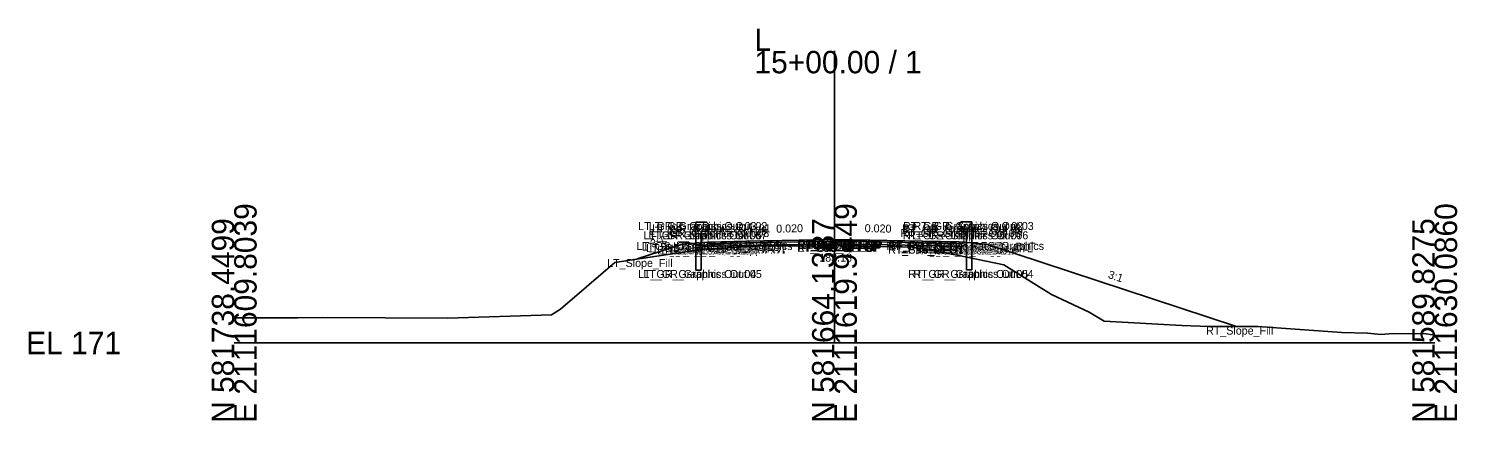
# Model space of a CAD drawing. Extents: x -26 to 3453, y -333 to 9539.
# Drawn here: x -25.7 to 152.8, y 5490.3 to 5539.3 of the extents above; entities that cross this region are included whole.
import ezdxf

# ---------------------------------------------------------------- set-up
doc = ezdxf.new("R2010")
doc.units = 0
for name, color, linetype in [('Default', 7, 'Continuous'), ('Exist Cross Section Cell', 7, 'Continuous'), ('Exist XS Center Line Elevation Label', 7, 'Continuous'), ('Exist XS Ground Line', 7, 'Continuous'), ('Prop CMT Guardrail Graphics', 7, 'Continuous'), ('Prop CMT Pvmt Course 1', 7, 'Continuous'), ('Prop CMT Pvmt Course 2', 7, 'Continuous'), ('Prop CMT Pvmt Course 3', 7, 'Continuous'), ('Prop CMT Pvmt Surface', 7, 'Continuous'), ('Prop CMT Pvmt Surface Shoulder', 7, 'Continuous'), ('Prop CMT Shld Paved Course 1', 7, 'Continuous'), ('Prop CMT Shld Paved Course 2', 7, 'Continuous'), ('Prop CMT Shld Paved Course 3', 7, 'Continuous'), ('Prop CMT Slope Grass', 7, 'Continuous'), ('Prop CMT Subgrade Earthwork', 7, 'Continuous'), ('Prop XS SE Text', 7, 'Continuous'), ('Prop XS Side Slope Text', 7, 'Continuous'), ('Scratch_Level_0', 7, 'Continuous')]:
    doc.layers.add(name, color=color, linetype=linetype)

msp = doc.modelspace()

# ---------------------------------------------------------------- linework, layer by layer
at = {"layer": 'Exist Cross Section Cell'}
for p, q in [((75, 5500), (75, 5536.54)), ((0, 5500), (75, 5500)), ((75, 5500), (150, 5500))]:
    msp.add_line(p, q, dxfattribs=at)
at = {"layer": 'Exist XS Ground Line'}
for p, q in [((47.57, 5510.09), (57.21, 5511.54)), ((57.21, 5511.54), (58.81, 5511.73)), ((58.81, 5511.73), (65.21, 5512.13)), ((65.21, 5512.13), (73.41, 5512.17)), ((73.41, 5512.17), (74.81, 5512.18)), ((74.81, 5512.18), (76.25, 5512.15)), ((76.25, 5512.15), (84.84, 5511.99)), ((84.84, 5511.99), (88.49, 5511.31)), ((88.49, 5511.31), (90.54, 5510.96)), ((40.79, 5504.24), (47.57, 5510.09)), ((90.54, 5510.96), (96.15, 5509.77)), ((96.15, 5509.77), (102.1, 5506.08)), ((102.1, 5506.08), (106.81, 5503.84)), ((39.65, 5503.54), (40.79, 5504.24)), ((0, 5503.15), (7.95, 5503.16)), ((7.95, 5503.16), (11.02, 5503.21)), ((11.02, 5503.21), (26.68, 5503.09)), ((26.68, 5503.09), (39.65, 5503.54)), ((106.81, 5503.84), (108.68, 5502.71)), ((108.68, 5502.71), (118.42, 5502.18)), ((118.42, 5502.18), (121.84, 5502.05)), ((121.84, 5502.05), (127.92, 5502.05)), ((127.92, 5502.05), (138.4, 5501.33)), ((138.4, 5501.33), (141.62, 5501.24)), ((141.62, 5501.24), (143.28, 5501.08)), ((143.28, 5501.08), (144.83, 5501.17)), ((144.83, 5501.17), (148.94, 5501.16)), ((148.94, 5501.16), (150, 5500.98))]:
    msp.add_line(p, q, dxfattribs=at)
at = {"layer": 'Prop CMT Guardrail Graphics'}
for points in [[(57.68, 5509.13), (57.68, 5515.13)], [(57.68, 5515.13), (59.01, 5515.13), (59.29, 5514.84)], [(92.15, 5515.14), (90.82, 5515.14), (90.55, 5514.84)], [(92.15, 5509.14), (92.15, 5515.14)], [(59.29, 5514.26), (59.01, 5513.97), (58.35, 5513.97)], [(58.35, 5513.97), (58.35, 5509.13)], [(59.29, 5514.84), (59.01, 5514.55)], [(59.01, 5514.55), (59.29, 5514.26)], [(90.55, 5514.84), (90.82, 5514.55)], [(90.82, 5514.55), (90.55, 5514.26)], [(90.55, 5514.26), (90.82, 5513.97), (91.49, 5513.97)], [(91.49, 5513.97), (91.49, 5509.14)], [(58.35, 5509.13), (57.68, 5509.13)], [(91.49, 5509.14), (92.15, 5509.14)]]:
    msp.add_lwpolyline(points, dxfattribs=at)
at = {"layer": 'Prop CMT Pvmt Course 1'}
for points in [[(75, 5512.95), (64, 5512.73)], [(64, 5512.52), (75, 5512.74)], [(64, 5512.73), (64, 5512.52)], [(75, 5512.74), (75, 5512.95)], [(75, 5512.95), (86, 5512.73)], [(75, 5512.74), (75, 5512.95)], [(86, 5512.52), (75, 5512.74)], [(86, 5512.73), (86, 5512.52)]]:
    msp.add_lwpolyline(points, dxfattribs=at)
msp.add_lwpolyline([(75, 5512.74), (75, 5512.82), (75, 5512.82), (75, 5512.74)], close=True, dxfattribs=at)
msp.add_lwpolyline([(75, 5512.74), (75, 5512.82), (75, 5512.82), (75, 5512.74)], close=True, dxfattribs=at)
at = {"layer": 'Prop CMT Pvmt Course 2'}
for points in [[(75, 5512.74), (64, 5512.52)], [(64, 5512.52), (64, 5512.19)], [(64, 5512.19), (75, 5512.41)], [(75, 5512.41), (75, 5512.74)], [(75, 5512.41), (75, 5512.74)], [(75, 5512.74), (86, 5512.52)], [(86, 5512.19), (75, 5512.41)], [(86, 5512.52), (86, 5512.19)]]:
    msp.add_lwpolyline(points, dxfattribs=at)
at = {"layer": 'Prop CMT Pvmt Course 3'}
for points in [[(75, 5512.41), (64, 5512.19)], [(64, 5512.19), (75, 5512.41)], [(64, 5512.19), (64, 5512.19)], [(75, 5512.41), (75, 5512.41)], [(75, 5512.41), (86, 5512.19)], [(86, 5512.19), (75, 5512.41)], [(75, 5512.41), (75, 5512.41)], [(86, 5512.19), (86, 5512.19)]]:
    msp.add_lwpolyline(points, dxfattribs=at)
at = {"layer": 'Prop CMT Pvmt Surface'}
for points in [[(75, 5512.95), (64, 5512.73)], [(75, 5512.95), (86, 5512.73)]]:
    msp.add_lwpolyline(points, dxfattribs=at)
at = {"layer": 'Prop CMT Pvmt Surface Shoulder'}
for points in [[(64, 5512.73), (59.3, 5512.63)], [(86, 5512.73), (90.54, 5512.64)]]:
    msp.add_lwpolyline(points, dxfattribs=at)
at = {"layer": 'Prop CMT Shld Paved Course 1'}
for points in [[(64, 5512.73), (59.3, 5512.63), (59.08, 5512.42)], [(59.08, 5512.42), (64, 5512.52)], [(64, 5512.52), (64, 5512.73)], [(86, 5512.73), (90.54, 5512.64), (90.75, 5512.42)], [(86, 5512.52), (86, 5512.73)], [(90.75, 5512.42), (86, 5512.52)]]:
    msp.add_lwpolyline(points, dxfattribs=at)
at = {"layer": 'Prop CMT Shld Paved Course 2'}
for points in [[(64, 5512.52), (59.08, 5512.42), (58.74, 5512.08)], [(58.74, 5512.08), (64, 5512.19)], [(64, 5512.19), (64, 5512.52)], [(86, 5512.52), (90.75, 5512.42), (91.09, 5512.08)], [(86, 5512.19), (86, 5512.52)], [(91.09, 5512.08), (86, 5512.19)]]:
    msp.add_lwpolyline(points, dxfattribs=at)
at = {"layer": 'Prop CMT Shld Paved Course 3'}
for points in [[(64, 5512.19), (58.74, 5512.08)], [(58.74, 5512.08), (64, 5512.19)], [(58.74, 5512.08), (58.74, 5512.08), (58.74, 5512.08)], [(64, 5512.19), (64, 5512.19)], [(86, 5512.19), (91.09, 5512.08)], [(91.09, 5512.08), (86, 5512.19)], [(86, 5512.19), (86, 5512.19)], [(91.09, 5512.08), (91.09, 5512.08), (91.09, 5512.08)]]:
    msp.add_lwpolyline(points, dxfattribs=at)
at = {"layer": 'Prop CMT Slope Grass'}
for points in [[(56, 5512.37), (50.37, 5510.51)], [(59.29, 5512.63), (56, 5512.37)], [(59.3, 5512.63), (59.29, 5512.63)], [(90.54, 5512.64), (90.55, 5512.64)], [(90.55, 5512.64), (94, 5512.36)], [(94, 5512.36), (125.25, 5502.05)]]:
    msp.add_lwpolyline(points, dxfattribs=at)
at = {"layer": 'Prop CMT Subgrade Earthwork'}
for points in [[(58.74, 5512.08), (58.27, 5512.55)], [(64, 5512.19), (58.74, 5512.08)], [(75, 5512.41), (64, 5512.19)], [(75, 5512.41), (86, 5512.19)], [(86, 5512.19), (91.09, 5512.08)], [(91.09, 5512.08), (91.56, 5512.55)]]:
    msp.add_lwpolyline(points, dxfattribs=at)

# ---------------------------------------------------------------- texts
at = {"layer": 'Default'}
msp.add_text('-', height=0.0001, dxfattribs=at).set_placement((0, 5500))
at = {"layer": 'Exist Cross Section Cell'}
for s, p in [('L', (65, 5536.54)), ('15+00.00 / 1', (65, 5533.74)), ('EL 171', (-26, 5498.6))]:
    msp.add_text(s, height=2.8, dxfattribs=at).set_placement(p)
for s, p in [('E 2111609.8039', (2.8, 5490)), ('E 2111619.9449', (77.8, 5490)), ('E 2111630.0860', (152.8, 5490)), ('N 581738.4499', (0, 5490)), ('N 581664.1387', (75, 5490)), ('N 581589.8275', (150, 5490))]:
    msp.add_text(s, height=2.8, rotation=90, dxfattribs=at).set_placement(p)
at = {"layer": 'Exist XS Center Line Elevation Label'}
msp.add_text('183.18', height=1, dxfattribs=at).set_placement((73.1, 5510.18))
at = {"layer": 'Prop XS SE Text'}
for rotation, p in [(1.1458, (67.73, 5513.8)), (358.8542, (78.77, 5513.87))]:
    msp.add_text('0.020', height=1, rotation=rotation, dxfattribs=at).set_placement(p)
at = {"layer": 'Prop XS Side Slope Text'}
for rotation, p in [(18.2629, (52.2, 5511.9)), (341.7371, (109.11, 5508.16))]:
    msp.add_text('3:1', height=1, rotation=rotation, dxfattribs=at).set_placement(p)
at = {"layer": 'Scratch_Level_0'}
for s, p in [('LT_GR_Graphics Out 03', (50.47, 5514.13)), ('LT_GR_Graphics Out 02', (51.82, 5514.13)), ('LT_GR_Graphics Out 01', (52.23, 5513.84)), ('RT_GR_Graphics Out 01', (83.44, 5513.84)), ('RT_GR_Graphics Out 02', (83.56, 5514.14)), ('RT_GR_Graphics Out 03', (84.88, 5514.14)), ('LT_GR_Graphics Out 06', (51.12, 5512.97)), ('LT_GR_Graphics Out 07', (51.77, 5512.97)), ('LT_GR_Graphics Out 09', (51.79, 5513.55)), ('LT_GR_Graphics Out 08', (52.06, 5513.26)), ('RT_GR_Graphics Out 08', (83.26, 5513.26)), ('RT_GR_Graphics Out 07', (83.52, 5512.97)), ('RT_GR_Graphics Out 09', (83.54, 5513.55)), ('RT_GR_Graphics Out 06', (84.2, 5512.97)), ('LT_GS_OS_GR_Face_Graphics', (50.28, 5511.63)), ('LT_Sub_Trench_Out_DLT', (50.92, 5511.55)), ('LT_GS_OS_CTL', (51.46, 5511.37)), ('LT_Sub_Trench_Out', (52.85, 5511.08)), ('LT_PS3_Shelf_Out', (53.4, 5511.08)), ('LT_PS3_OEOP', (54.53, 5511.08)), ('LT_PS2_OEOP', (54.87, 5511.42)), ('LT_PS1_OEOP', (55.2, 5511.63)), ('LT_PV2_OEOT', (59.75, 5511.52)), ('LT_PV3_OEOT', (59.75, 5511.19)), ('LT_Sub_OEOT', (59.77, 5511.19)), ('LT_PV1_OEOT', (59.87, 5511.73)), ('RT_PV2_OEEOP', (70.33, 5511.74)), ('RT_PV3_OEEOP', (70.33, 5511.41)), ('RT_Sub_OEEOP', (70.36, 5511.41)), ('LT_PV2_OEEOP', (70.39, 5511.74)), ('LT_PV3_OEEOP', (70.39, 5511.41)), ('LT_Sub_OEEOP', (70.42, 5511.41)), ('RT_PV1_OEEOP', (70.45, 5511.82)), ('LT_PV1_OEEOP', (70.51, 5511.82)), ('RT_PV2_IEEOP', (70.71, 5511.74)), ('LT_PV2_IEEOP', (70.77, 5511.74)), ('RT_PV1_IEEOP', (70.83, 5511.82)), ('LT_PV1_IEEOP', (70.89, 5511.82)), ('PV2_PGL', (72.35, 5511.74)), ('PV1_PGL', (72.47, 5511.95)), ('RT_GS_OS_GR_Face_Graphics', (81.49, 5511.64)), ('RT_PV2_OEOT', (81.69, 5511.52)), ('RT_PV3_OEOT', (81.69, 5511.19)), ('RT_Sub_OEOT', (81.71, 5511.19)), ('RT_PV1_OEOT', (81.81, 5511.73)), ('RT_Sub_Trench_Out_DLT', (84.15, 5511.55)), ('RT_Sub_Trench_Out', (85.14, 5511.08)), ('RT_PS3_Shelf_Out', (85.69, 5511.08)), ('RT_PS1_OEOP', (86.39, 5511.64)), ('RT_PS2_OEOP', (86.48, 5511.42)), ('RT_PS3_OEOP', (86.82, 5511.08)), ('RT_GS_OS_CTL', (89.4, 5511.36)), ('LT_Slope_Fill', (46.6, 5509.51)), ('LT_GR_Graphics Out 04', (50.45, 5508.13)), ('LT_GR_Graphics Out 05', (51.13, 5508.13)), ('RT_GR_Graphics Out 05', (84.21, 5508.14)), ('RT_GR_Graphics Out 04', (84.86, 5508.14)), ('RT_Slope_Fill', (121.43, 5501.05))]:
    msp.add_text(s, height=1, dxfattribs=at).set_placement(p)

doc.saveas('drawing.dxf')
